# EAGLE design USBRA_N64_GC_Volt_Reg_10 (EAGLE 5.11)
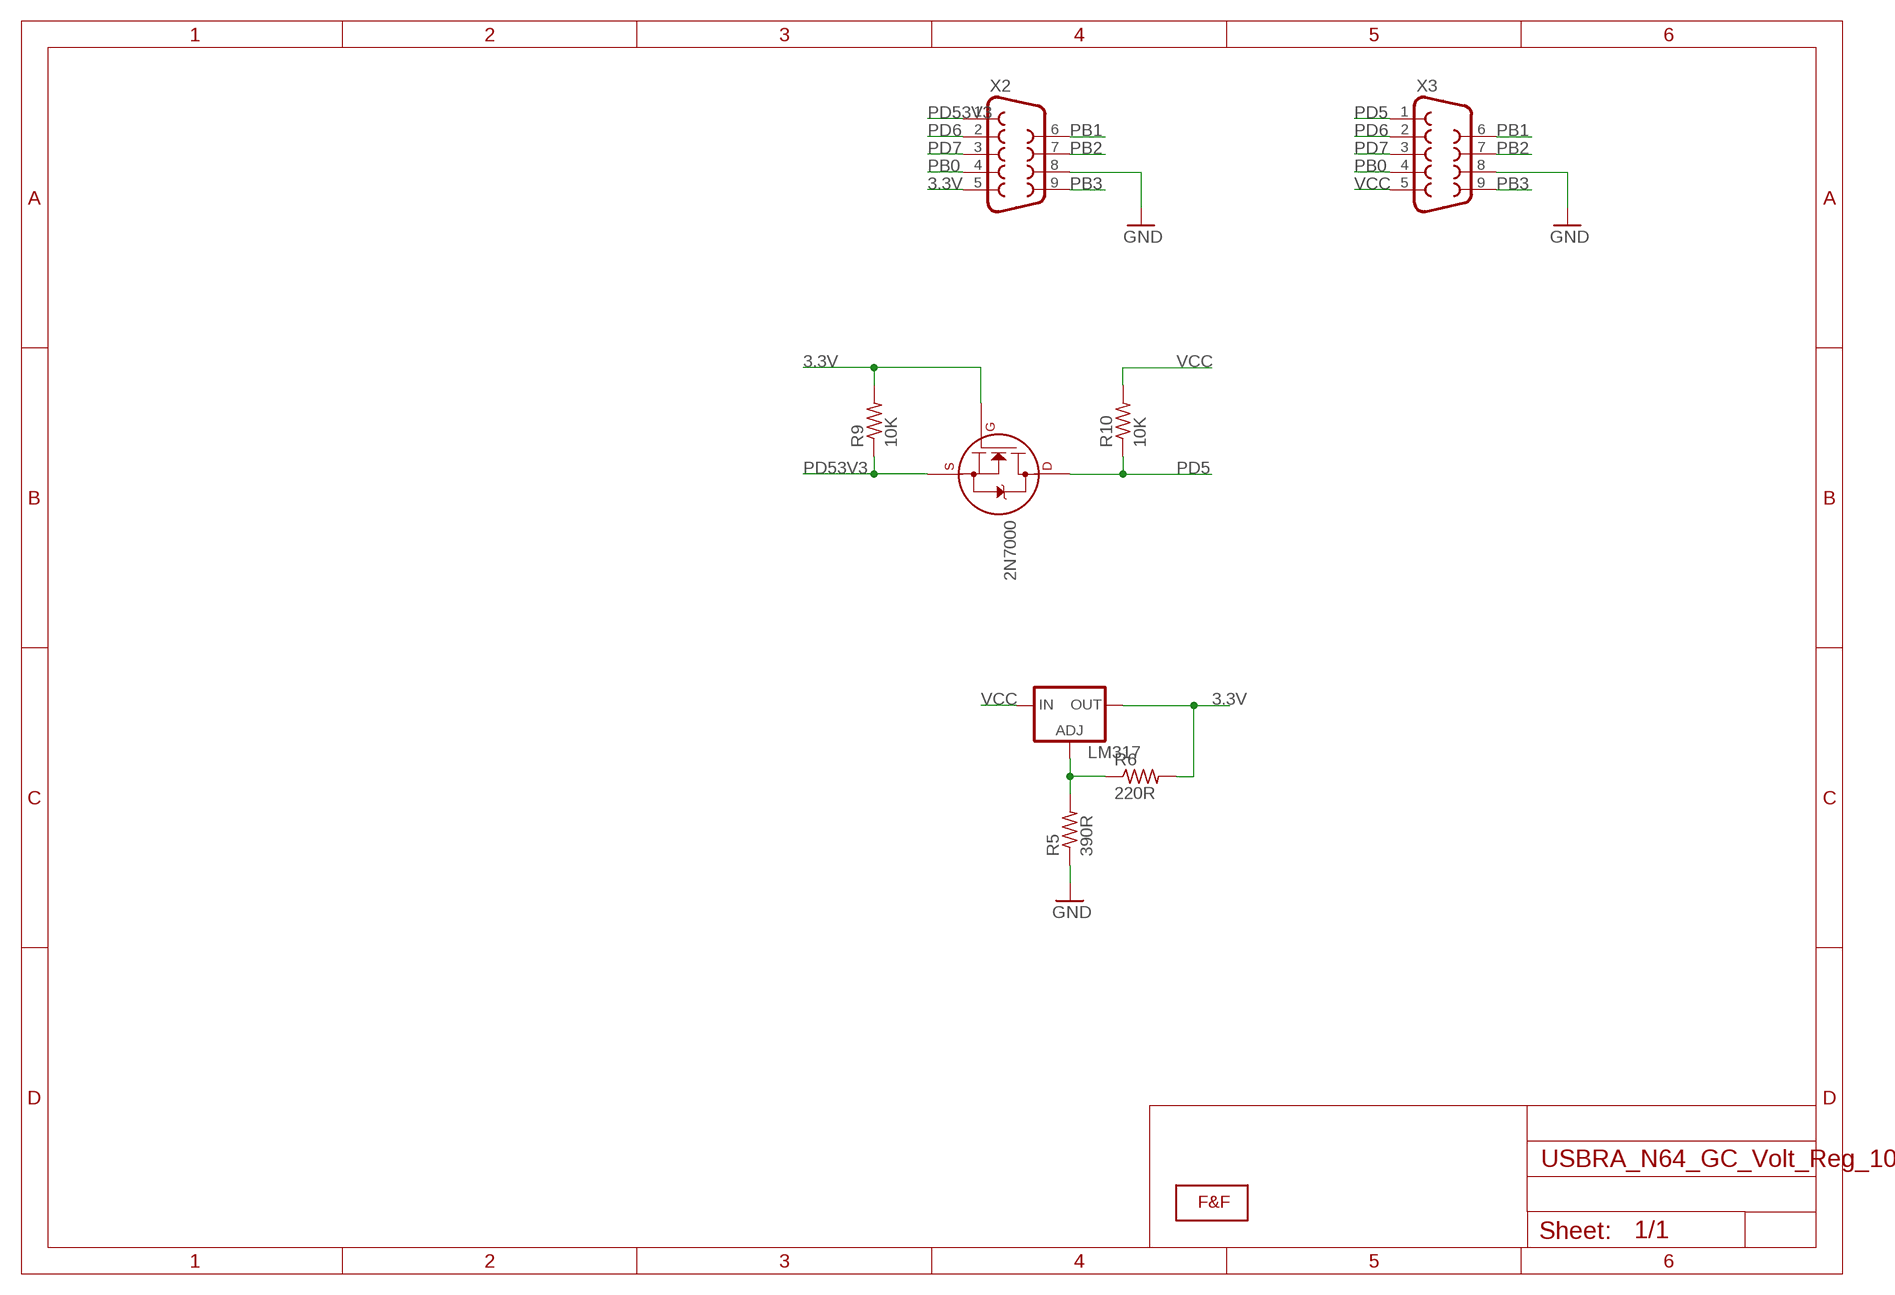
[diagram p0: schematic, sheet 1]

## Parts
2N7000  2N7000_TO92  [TO-92]
LM317  LM317TS  [317TS]
R5  390R  R-US_0207/10  [0207/10]
R6  220R  R-US_0207/10  [0207/10]
R9  10K  R-US_0207/10  [0207/10]
R10  10K  R-US_0207/10  [0207/10]
U$1  LOGOLOGO_WITH_SMOKE_BIG  [LOGO_BIG]
X2  DB9MALE  [DB9_MALE]
X3  DB9FEMALE  [DB9]

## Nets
3.3V: 2N7000.2(G) LM317.2(OUT) R6.2 R9.2 X2.5
GND: R5.1 X2.8 X3.8
N$5: LM317.1(ADJ) R5.2 R6.1
PB0: X2.4 X3.4
PB1: X2.6 X3.6
PB2: X2.7 X3.7
PB3: X2.9 X3.9
PD5: 2N7000.3(D) R10.1 X3.1
PD6: X2.2 X3.2
PD7: X2.3 X3.3
PD53V3: 2N7000.1(S) R9.1 X2.1
VCC: LM317.3(IN) R10.2 X3.5

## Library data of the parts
2N7000 = transistors:2N700*: 2N7000, 2N7002, NDS7002A N-channel enhancement mode MOSFET
LM317 = v-reg:LM317TS: VOLTAGE REGULATOR
R5 R6 R9 R10 = adafruit:R-US_: RESISTOR, American symbol
U$1 = F&F:LOGO: Faísca e Fumaça Logo
X2 X3 = SparkFun:DB9: DB9 Connector Standard DB9 (D-Sub 9) serial connector. Can be used for CAN bus as well as RS485 and RS232. Footprint production proven. Spark Fun Electronics SKU : PRT-00429

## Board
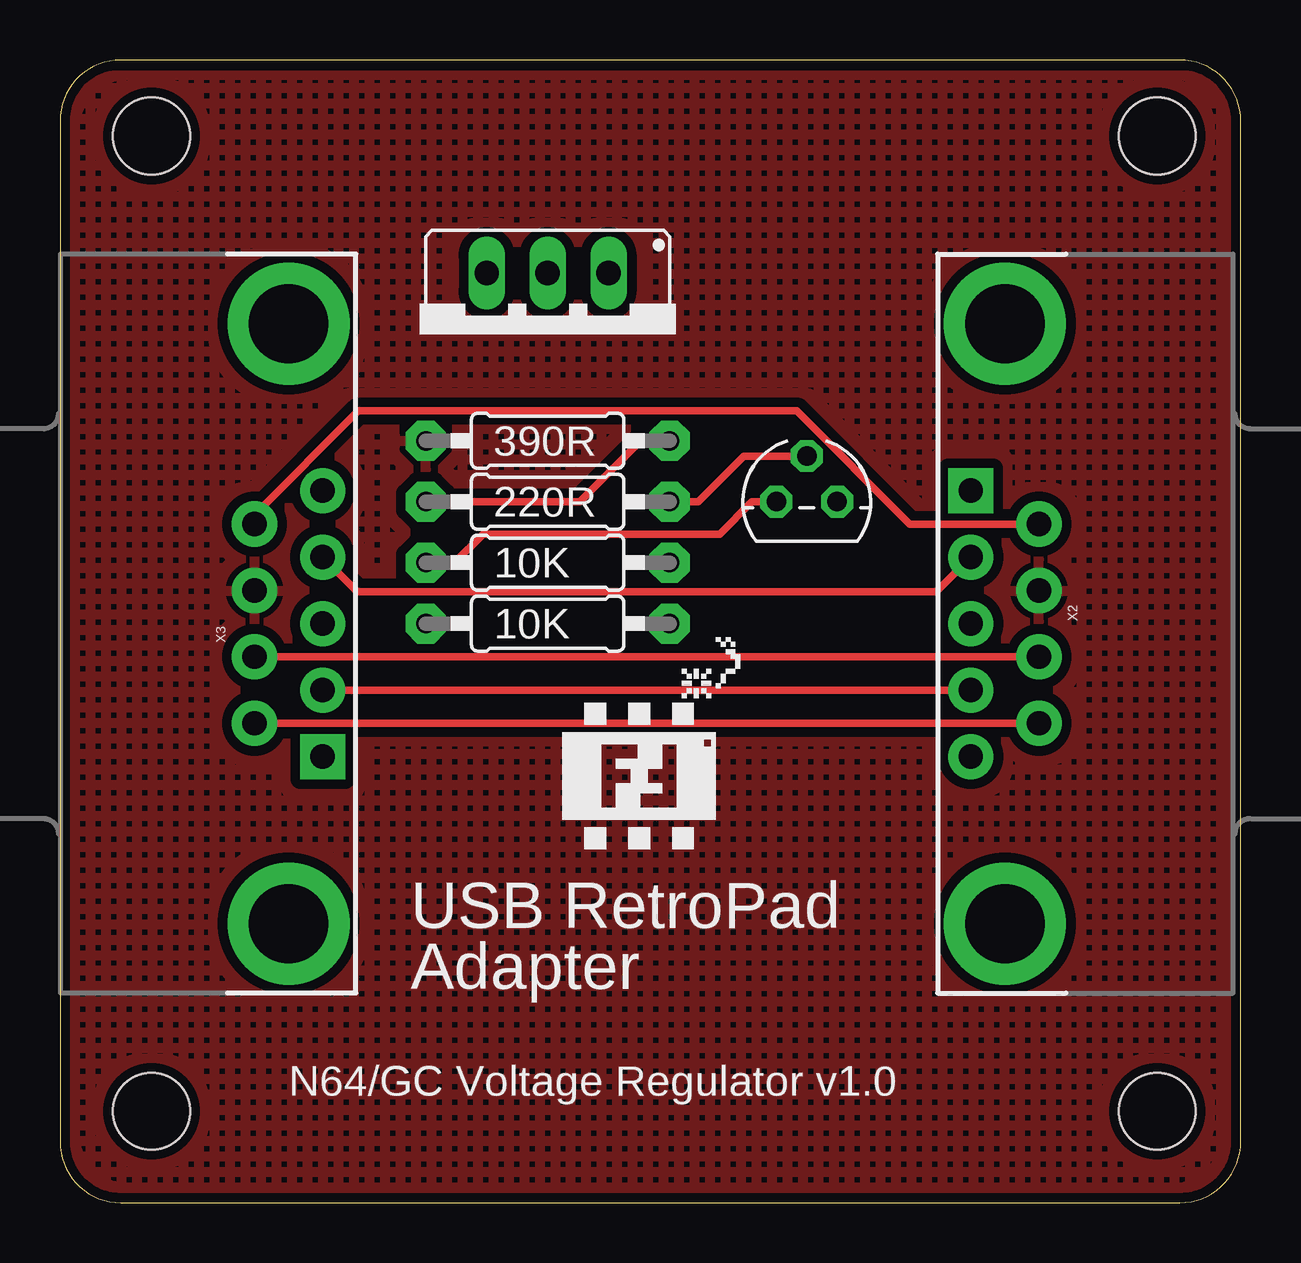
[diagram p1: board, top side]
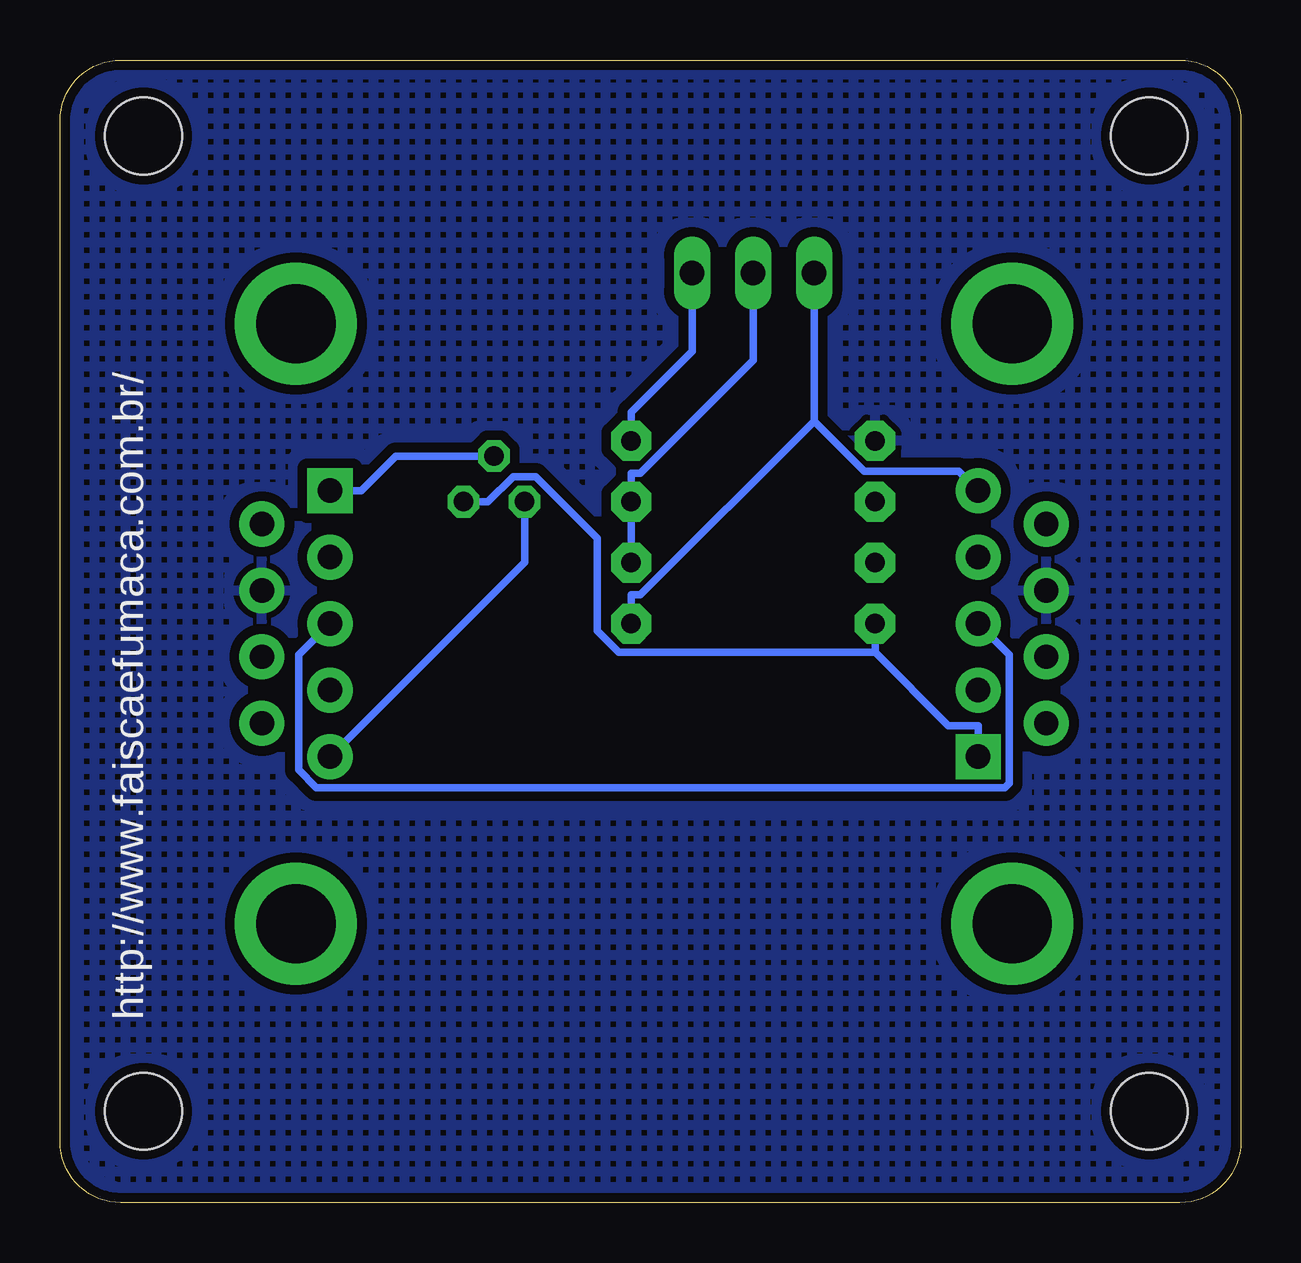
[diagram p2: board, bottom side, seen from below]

Size 49.2 x 47.62 mm. Coordinates in mm from the lower left corner, seen from the top.
Outline: 49.2,45.08 arc90 46.66,47.62 2.54,47.62 arc90 0,45.08 0,2.54 arc90 2.54,0 46.66,0 arc90 49.2,2.54 49.2,45.08
Copper layers (1*16): Top 0.035mm / dielectric 1.5mm / Bottom 0.035mm
Design rules "Fusion_eagle_rule_v1.1": minimum track width 6mil, minimum drill 12mil, track to track 6mil, track to pad 6mil, pad to pad 6mil, via to via 6mil, smd to smd 0mil, copper to edge 10mil, drill to drill 10mil, minimum pad ring 10mil, minimum via ring 6mil, stop-mask expansion 2mil, vias tented up to drill 100mil, thermal gap 10mil
Holes 3.2 mm at 3.81,44.45 3.81,3.81 45.72,44.45 45.72,3.81

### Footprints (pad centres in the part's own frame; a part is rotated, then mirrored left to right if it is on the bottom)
TO-92 = drill 0.813 octagon: 1 -1.27,0; 2 0,1.905; 3 1.27,0
317TS = drill 1.016 long: 1 -2.54,-2.54; 2 0,-2.54; 3 2.54,-2.54
0207/10 = drill 0.813 pad 1.676 octagon: 1 -5.08,0; 2 5.08,0
DB9_MALE = drill 1.016 pad 1.88 round: 1 5.54,-1.42; 2 2.77,-1.42; 3 0,-1.42; 4 -2.77,-1.42; 6 4.15,1.42; 7 1.38,1.42; 8 -1.38,1.42; 9 -4.15,1.42 | drill 1.016 pad 1.88 square: 5 -5.54,-1.42 | drill 3.302 pad 5.08 round: G1 -12.5,0; G2 12.5,0
DB9 = drill 1.016 pad 1.88 square: 1 -5.54,-1.42 | drill 1.016 pad 1.88 round: 2 -2.77,-1.42; 3 0,-1.42; 4 2.77,-1.42; 5 5.54,-1.42; 6 -4.15,1.42; 7 -1.38,1.42; 8 1.38,1.42; 9 4.15,1.42 | drill 3.302 pad 5.08 round: G1 -12.5,0; G2 12.5,0

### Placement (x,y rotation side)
2N7000  31.11,29.21 0 top
LM317  20.32,36.2 180 top
R5  20.32,31.75 0 top
R6  20.32,29.21 0 top
R9  20.32,26.67 0 top
R10  20.32,24.13 0 top
U$1  24.13,17.78 0 top
X2  39.37,24.13 270 top
X3  9.53,24.13 90 top

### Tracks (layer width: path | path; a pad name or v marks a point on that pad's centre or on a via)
3.3V
  Top 0.305: R6.2 26.59,29.21 28.5,31.11 2N7000.2
  Bottom 0.305: LM317.2 20.32,35.11 25.03,30.4 25.4,30.4 R6.2 R9.2 | X2.5 36.65,29.67 35.21,31.11 2N7000.2
GND
  pour Bottom (isolate 0.406, hatched): 0,46.99 49.53,46.99 49.53,0 0,0
  pour Top (isolate 0.406, hatched): 0,46.99 49.53,46.99 49.53,0 0,0
N$5
  Top 0.305: R5.2 24.21,31.75 21.67,29.21 R6.1
  Bottom 0.305: R5.2 25.4,32.94 22.86,35.48 LM317.1
PB0
  Top 0.305: X3.4 12.38,25.46 36.51,25.46 X2.4
PB1
  Top 0.305: X3.6 X2.6
PB2
  Top 0.305: X3.7 X2.7
PB3
  Top 0.305: X3.9 8.11,28.66 12.43,32.99 30.7,32.99 35.41,28.28 X2.9
PD5
  Bottom 0.305: 2N7000.3 31.37,29.21 30.32,30.25 29.38,30.25 26.81,27.68 26.81,23.83 25.92,22.94 15.24,22.94 | 15.24,22.94 15.24,23.06 R10.1 | X3.1 10.95,19.89 12.19,19.89 15.24,22.94
PD6
  Top 0.305: X3.2 X2.2
PD7
  Bottom 0.305: X3.3 9.65,22.83 9.65,17.47 9.83,17.29 38.51,17.29 39.25,18.03 39.25,22.83 X2.3
PD53V3
  Top 0.305: 2N7000.1 28.83,29.21 27.48,27.86 17.63,27.86 16.43,26.67 R9.1
  Bottom 0.305: X2.1 29.84,26.7 2N7000.1
VCC
  Bottom 0.305: 17.78,32.57 LM317.3 | 17.78,32.57 25.03,25.32 25.4,25.32 R10.2 | X3.5 11.76,30.48 15.69,30.48 17.78,32.57

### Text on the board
tPlace: USB RetroPad | Adapter | N64/GC Voltage Regulator v1.0
bPlace: http://www.faiscaefumaca.com.br/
